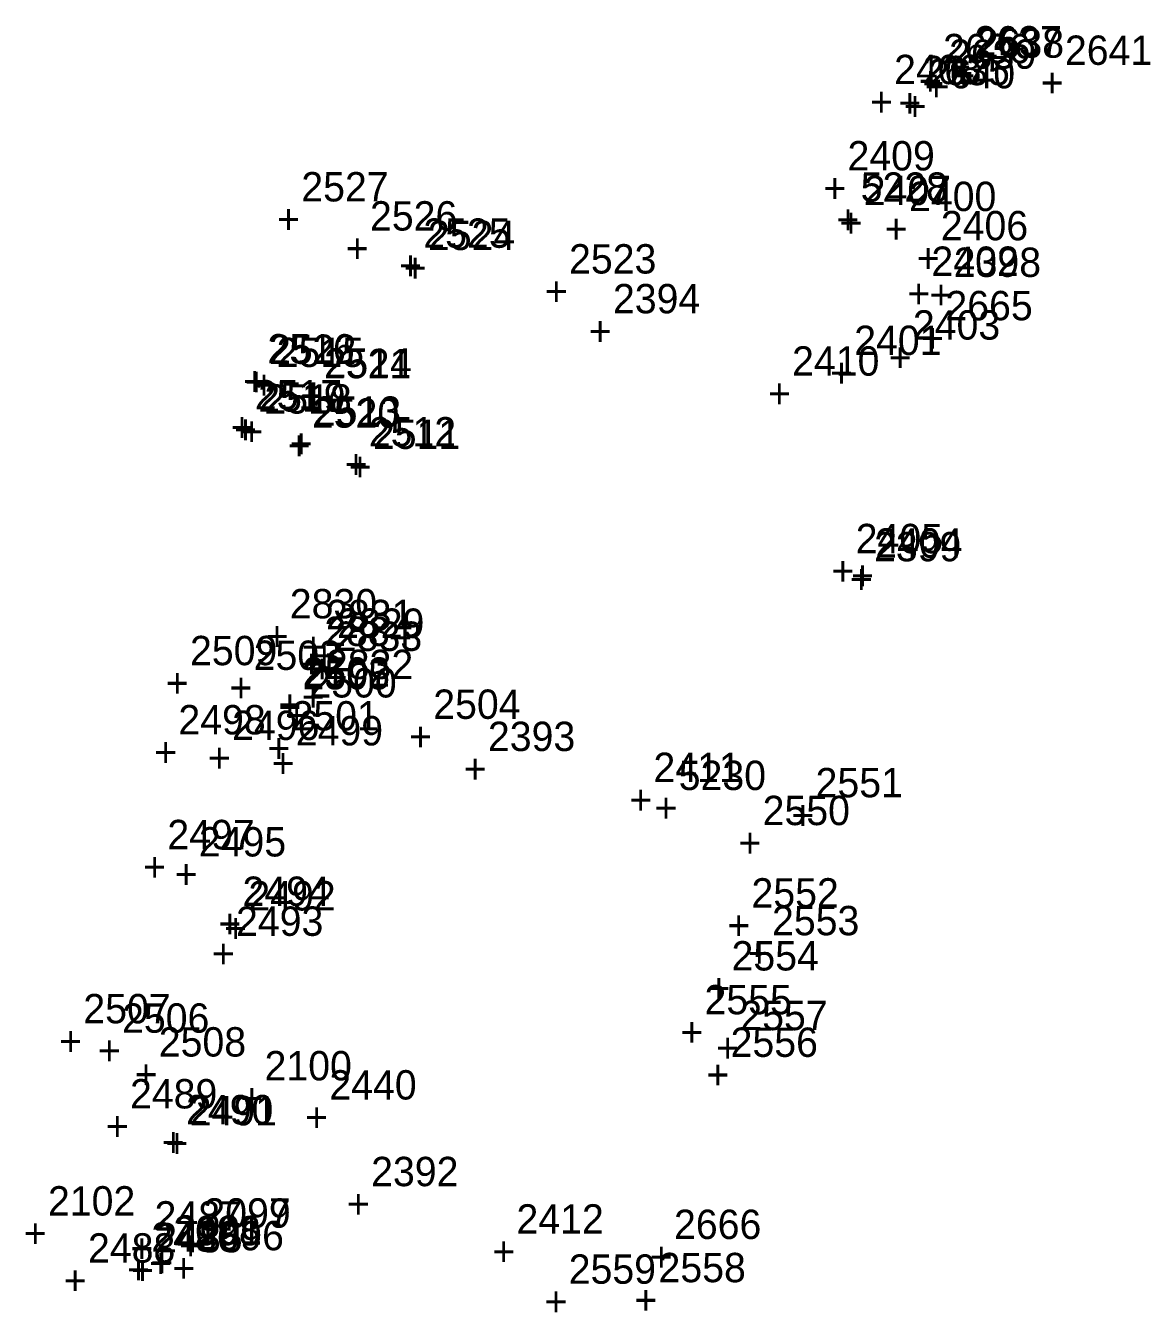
# Model space of a CAD drawing. Extents: x 1136220 to 1137808, y 528804 to 531215.
# Drawn here: x 1136904 to 1136999.8, y 529366.2 to 529475.8 of the extents above; entities that cross this region are included whole.
import ezdxf

# ---------------------------------------------------------------- set-up
doc = ezdxf.new("R2010")
doc.units = 0
for name, color, linetype in [('S_Buildings', 7, 'Continuous'), ('S_Buildings_SillElevation', 7, 'Continuous'), ('S_Buildings_Steps_Brick', 7, 'Continuous'), ('S_Curb_Type_3', 7, 'Continuous'), ('S_Drainage_CB', 7, 'Continuous'), ('S_Drainage_Culvert_Top', 7, 'Continuous'), ('S_Drainage_Invert', 7, 'Continuous'), ('S_Drainage_Sump', 7, 'Continuous'), ('S_Ground_Elevation', 7, 'Continuous'), ('S_Ground_SpotElevation', 7, 'Continuous'), ('S_Property_ConcPad', 7, 'Continuous'), ('S_Property_Walkways', 7, 'Continuous'), ('S_Roadway_Centerline', 7, 'Continuous'), ('S_Roadway_Drive_Paved', 7, 'Continuous'), ('S_Roadway_Edge_Pavement', 7, 'Continuous'), ('S_Utilities_Pole_Joint', 7, 'Continuous'), ('S_Utilities_UG_Gas_Line', 7, 'Continuous'), ('S_Utilities_UG_Sanitary_MH', 7, 'Continuous'), ('S_Utilities_UG_Water_Line', 7, 'Continuous'), ('S_Utilities_UG_Water_Shutoff', 7, 'Continuous')]:
    doc.layers.add(name, color=color, linetype=linetype)

msp = doc.modelspace()

# ---------------------------------------------------------------- texts
at = {"layer": 'S_Buildings'}
for s, p in [('2398', (1136983.07, 529454.42)), ('+', (1136981.01, 529451.67)), ('2399', (1136976.28, 529430.2)), ('+', (1136974.22, 529427.45)), ('2557', (1136964.89, 529390.27)), ('+', (1136962.83, 529387.52))]:
    msp.add_text(s, height=2.5, dxfattribs=at).set_placement(p)
at = {"layer": 'S_Buildings_SillElevation'}
for s, p in [('2665', (1136982.36, 529450.73)), ('+', (1136980.29, 529447.98)), ('2666', (1136959.24, 529372.48)), ('+', (1136957.18, 529369.73))]:
    msp.add_text(s, height=2.5, dxfattribs=at).set_placement(p)
at = {"layer": 'S_Buildings_Steps_Brick'}
for s, p in [('2516', (1136924.6, 529447.05)), ('2515', (1136925.39, 529446.75)), ('2514', (1136929.47, 529445.83)), ('+', (1136922.54, 529444.3)), ('+', (1136923.33, 529444)), ('2517', (1136923.53, 529443.13)), ('2518', (1136924.35, 529442.78)), ('+', (1136927.41, 529443.08)), ('2513', (1136928.56, 529441.74)), ('+', (1136921.47, 529440.38)), ('+', (1136922.29, 529440.03)), ('+', (1136926.5, 529438.99))]:
    msp.add_text(s, height=2.5, dxfattribs=at).set_placement(p)
at = {"layer": 'S_Curb_Type_3'}
for s, p in [('2639', (1136982.67, 529472.15)), ('2638', (1136985.03, 529473.09)), ('2640', (1136980.86, 529470.48)), ('+', (1136980.61, 529469.4)), ('+', (1136982.96, 529470.34)), ('+', (1136978.8, 529467.73)), ('2525', (1136937.88, 529456.9)), ('+', (1136935.82, 529454.15)), ('2512', (1136933.24, 529439.98)), ('+', (1136931.18, 529437.23)), ('2502', (1136927.6, 529419.52)), ('+', (1136925.54, 529416.77)), ('2501', (1136926.66, 529415.79)), ('+', (1136924.6, 529413.04)), ('2494', (1136922.48, 529400.85)), ('+', (1136920.42, 529398.1)), ('2493', (1136921.93, 529398.3)), ('+', (1136919.87, 529395.55)), ('2490', (1136917.67, 529382.25)), ('+', (1136915.61, 529379.5)), ('2487', (1136914.99, 529373.2)), ('2486', (1136914.71, 529371.4)), ('+', (1136912.93, 529370.45)), ('+', (1136912.65, 529368.65))]:
    msp.add_text(s, height=2.5, dxfattribs=at).set_placement(p)
at = {"layer": 'S_Drainage_CB'}
for s, p in [('2829', (1136930.54, 529423.68)), ('+', (1136928.48, 529420.93))]:
    msp.add_text(s, height=2.5, dxfattribs=at).set_placement(p)
at = {"layer": 'S_Drainage_Culvert_Top'}
for s, p in [('2830', (1136926.51, 529425.34)), ('+', (1136924.45, 529422.59)), ('2832', (1136929.59, 529420.17)), ('+', (1136927.53, 529417.42)), ('2100', (1136924.36, 529385.99)), ('+', (1136922.3, 529383.24)), ('2102', (1136905.91, 529374.48)), ('2099', (1136919.15, 529373.44)), ('2101', (1136916.7, 529372)), ('+', (1136903.85, 529371.73)), ('+', (1136917.09, 529370.69)), ('+', (1136914.64, 529369.25))]:
    msp.add_text(s, height=2.5, dxfattribs=at).set_placement(p)
at = {"layer": 'S_Drainage_Invert'}
for s, p in [('2831', (1136929.6, 529424.42)), ('2833', (1136930.35, 529422.57)), ('+', (1136927.54, 529421.67)), ('+', (1136928.29, 529419.82)), ('2097', (1136919.15, 529373.45)), ('2098', (1136916.59, 529371.94)), ('+', (1136917.09, 529370.7)), ('+', (1136914.53, 529369.19))]:
    msp.add_text(s, height=2.5, dxfattribs=at).set_placement(p)
at = {"layer": 'S_Drainage_Sump'}
for s, p in [('2834', (1136929.45, 529422.99)), ('+', (1136927.38, 529420.24))]:
    msp.add_text(s, height=2.5, dxfattribs=at).set_placement(p)
at = {"layer": 'S_Ground_Elevation'}
for s, p in [('2522', (1136924.74, 529447.01)), ('2521', (1136929.42, 529445.79)), ('+', (1136922.68, 529444.26)), ('2519', (1136923.82, 529442.94)), ('+', (1136927.36, 529443.04)), ('2520', (1136928.39, 529441.58)), ('+', (1136921.76, 529440.19)), ('+', (1136926.33, 529438.83))]:
    msp.add_text(s, height=2.5, dxfattribs=at).set_placement(p)
at = {"layer": 'S_Ground_SpotElevation'}
for s, p in [('2527', (1136927.49, 529460.85)), ('+', (1136925.43, 529458.1)), ('2509', (1136918.01, 529421.35)), ('+', (1136915.95, 529418.6)), ('2551', (1136971.3, 529410.1)), ('2550', (1136966.79, 529407.73)), ('+', (1136969.24, 529407.35)), ('+', (1136964.73, 529404.98)), ('2552', (1136965.84, 529400.71)), ('+', (1136963.78, 529397.96)), ('2507', (1136908.92, 529390.85)), ('2506', (1136912.22, 529390.05)), ('+', (1136906.86, 529388.1)), ('+', (1136910.16, 529387.3)), ('2558', (1136957.92, 529368.8)), ('+', (1136955.86, 529366.05))]:
    msp.add_text(s, height=2.5, dxfattribs=at).set_placement(p)
at = {"layer": 'S_Property_ConcPad'}
for s, p in [('2402', (1136981.17, 529454.51)), ('+', (1136979.11, 529451.76)), ('2403', (1136979.59, 529449.08)), ('+', (1136977.53, 529446.33))]:
    msp.add_text(s, height=2.5, dxfattribs=at).set_placement(p)
at = {"layer": 'S_Property_Walkways'}
for s, p in [('2526', (1136933.34, 529458.37)), ('+', (1136931.28, 529455.62)), ('2503', (1136923.43, 529420.95)), ('+', (1136921.37, 529418.2)), ('2496', (1136921.59, 529414.98)), ('+', (1136919.53, 529412.23)), ('2495', (1136918.76, 529405.06)), ('+', (1136916.7, 529402.31)), ('2489', (1136912.9, 529383.6)), ('+', (1136910.84, 529380.85)), ('2488', (1136909.32, 529370.47)), ('+', (1136907.25, 529367.72))]:
    msp.add_text(s, height=2.5, dxfattribs=at).set_placement(p)
at = {"layer": 'S_Roadway_Centerline'}
for s, p in [('2394', (1136954.04, 529451.32)), ('+', (1136951.98, 529448.57)), ('2393', (1136943.39, 529414.04)), ('+', (1136941.33, 529411.29)), ('2392', (1136933.44, 529376.98)), ('+', (1136931.37, 529374.23))]:
    msp.add_text(s, height=2.5, dxfattribs=at).set_placement(p)
at = {"layer": 'S_Roadway_Drive_Paved'}
for s, p in [('2498', (1136917.02, 529415.46)), ('+', (1136914.96, 529412.71)), ('2497', (1136916.08, 529405.68)), ('+', (1136914.02, 529402.93))]:
    msp.add_text(s, height=2.5, dxfattribs=at).set_placement(p)
at = {"layer": 'S_Roadway_Edge_Pavement'}
for s, p in [('2637', (1136984.84, 529473.28)), ('2636', (1136982.16, 529472.62)), ('2641', (1136992.54, 529472.48)), ('2408', (1136977.99, 529470.84)), ('2635', (1136980.41, 529470.75)), ('+', (1136982.78, 529470.53)), ('+', (1136980.1, 529469.87)), ('+', (1136990.48, 529469.73)), ('+', (1136975.93, 529468.09)), ('+', (1136978.35, 529468)), ('5228', (1136975.14, 529460.82)), ('2407', (1136975.4, 529460.54)), ('+', (1136973.08, 529458.07)), ('+', (1136973.34, 529457.79)), ('2406', (1136981.97, 529457.54)), ('2524', (1136938.28, 529456.71)), ('+', (1136936.22, 529453.96)), ('+', (1136979.91, 529454.79)), ('2511', (1136933.59, 529439.77)), ('+', (1136931.52, 529437.02)), ('2405', (1136974.72, 529430.89)), ('2404', (1136976.38, 529430.51)), ('+', (1136972.65, 529428.14)), ('+', (1136974.32, 529427.76)), ('2500', (1136928.18, 529418.6)), ('+', (1136926.12, 529415.85)), ('2499', (1136927.02, 529414.52)), ('+', (1136924.96, 529411.77)), ('5230', (1136959.64, 529410.72)), ('+', (1136957.58, 529407.97)), ('2492', (1136922.98, 529400.46)), ('2553', (1136967.59, 529398.35)), ('+', (1136920.92, 529397.71)), ('2554', (1136964.14, 529395.35)), ('+', (1136965.53, 529395.6)), ('+', (1136962.08, 529392.6)), ('2555', (1136961.84, 529391.62)), ('+', (1136959.78, 529388.87)), ('2556', (1136964.06, 529387.99)), ('+', (1136962, 529385.24)), ('2491', (1136917.98, 529382.16)), ('+', (1136915.92, 529379.41)), ('2485', (1136915.05, 529371.34)), ('+', (1136912.99, 529368.59))]:
    msp.add_text(s, height=2.5, dxfattribs=at).set_placement(p)
at = {"layer": 'S_Utilities_Pole_Joint'}
for s, p in [('2400', (1136979.26, 529460.03)), ('+', (1136977.19, 529457.28))]:
    msp.add_text(s, height=2.5, dxfattribs=at).set_placement(p)
at = {"layer": 'S_Utilities_UG_Gas_Line'}
for s, p in [('2409', (1136974.02, 529463.49)), ('+', (1136971.96, 529460.74)), ('2410', (1136969.3, 529446.01)), ('+', (1136967.24, 529443.26)), ('2411', (1136957.49, 529411.4)), ('+', (1136955.43, 529408.65)), ('2412', (1136945.82, 529372.94)), ('+', (1136943.76, 529370.19))]:
    msp.add_text(s, height=2.5, dxfattribs=at).set_placement(p)
at = {"layer": 'S_Utilities_UG_Sanitary_MH'}
for s, p in [('2096', (1136918.57, 529371.52)), ('+', (1136916.5, 529368.77))]:
    msp.add_text(s, height=2.5, dxfattribs=at).set_placement(p)
at = {"layer": 'S_Utilities_UG_Water_Line'}
for s, p in [('2523', (1136950.3, 529454.71)), ('+', (1136948.24, 529451.96)), ('2505', (1136927.6, 529419.29)), ('2504', (1136938.73, 529416.78)), ('+', (1136925.54, 529416.54)), ('+', (1136936.67, 529414.03)), ('2440', (1136929.88, 529384.36)), ('+', (1136927.82, 529381.61))]:
    msp.add_text(s, height=2.5, dxfattribs=at).set_placement(p)
at = {"layer": 'S_Utilities_UG_Water_Shutoff'}
for s, p in [('2401', (1136974.59, 529447.77)), ('+', (1136972.53, 529445.02)), ('2508', (1136915.35, 529388.02)), ('+', (1136913.29, 529385.27)), ('2559', (1136950.27, 529368.67)), ('+', (1136948.21, 529365.92))]:
    msp.add_text(s, height=2.5, dxfattribs=at).set_placement(p)

doc.saveas('drawing.dxf')
